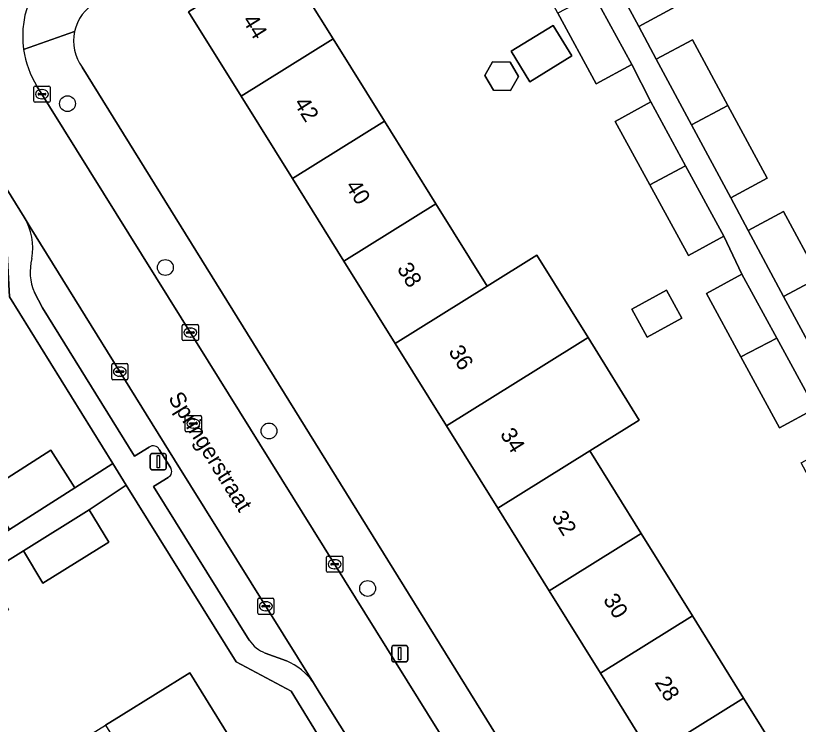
# Model space of a CAD drawing. Extents: x 160030 to 160839, y 385325 to 386450.
# Drawn here: x 160337.33 to 160385.75, y 386132 to 386175.84 of the extents above; entities that cross this region are included whole.
import ezdxf

# ---------------------------------------------------------------- set-up
doc = ezdxf.new("R2010")
doc.units = 0
for name, color, linetype in [('IMGEO_Boom', 7, 'Continuous'), ('IMGEO_Erf', 7, 'Continuous'), ('IMGEO_Kolk', 7, 'Continuous'), ('IMGEO_Lichtmast', 7, 'Continuous'), ('IMGEO_Openbare_ruimte_label', 7, 'Continuous'), ('IMGEO_Pand', 7, 'Continuous'), ('IMGEO_Pand_nummerreeks', 7, 'Continuous'), ('IMGEO_Parkeervlak_open', 7, 'Continuous'), ('IMGEO_Rijbaan_lokaal_open', 7, 'Continuous'), ('IMGEO_Rioolput', 7, 'Continuous'), ('IMGEO_Voetpad_open', 7, 'Continuous')]:
    doc.layers.add(name, color=color, linetype=linetype)

msp = doc.modelspace()

# ---------------------------------------------------------------- linework, layer by layer
at = {"layer": 'IMGEO_Boom'}
for centre in [(160340.54, 386170.396), (160346.596, 386160.261), (160353.007, 386150.151), (160359.103, 386140.41)]:
    msp.add_circle(centre, 0.489, dxfattribs=at)
at = {"layer": 'IMGEO_Erf'}
for points in [[(160386.456, 386204.216), (160366.397, 386191.699), (160368.364, 386188.756), (160370.398, 386190.026), (160372.892, 386185.907), (160370.857, 386184.636), (160371.277, 386183.751), (160373.496, 386184.948), (160375.684, 386180.893), (160378.121, 386176.378), (160375.889, 386175.174), (160376.956, 386173.146), (160379.191, 386174.352), (160381.389, 386170.279), (160383.816, 386165.782), (160381.567, 386164.569), (160382.635, 386162.54), (160384.828, 386163.723), (160387.034, 386159.635)], [(160380.059, 386158.644), (160382.254, 386159.841), (160381.145, 386162.194), (160378.95, 386160.997), (160376.563, 386165.373), (160374.42, 386169.302), (160376.615, 386170.499), (160375.446, 386172.828), (160373.251, 386171.631), (160370.876, 386175.985), (160368.721, 386179.936), (160370.916, 386181.133), (160369.675, 386183.865), (160367.589, 386182.567), (160365.026, 386186.686), (160367.112, 386187.984), (160365.243, 386190.979), (160342.312, 386176.669)], [(160376.673, 386130.076), (160373.499, 386135.173), (160370.324, 386140.271), (160367.15, 386145.368), (160363.976, 386150.466), (160360.802, 386155.563), (160357.628, 386160.661), (160354.453, 386165.759), (160351.279, 386170.856), (160348.03, 386176.074), (160353.721, 386179.618), (160356.97, 386174.4), (160360.144, 386169.303), (160363.319, 386164.205), (160366.493, 386159.107), (160369.564, 386161.019), (160372.737, 386155.922), (160375.911, 386150.824), (160372.841, 386148.912), (160376.015, 386143.815), (160379.19, 386138.717), (160382.364, 386133.62), (160385.538, 386128.522)], [(160341.444, 386172.646), (160376.697, 386115.797)], [(160323.179, 386138.988), (160324.786, 386136.357), (160326.683, 386137.623), (160325.077, 386140.255), (160329.187, 386142.765), (160333.374, 386145.322), (160334.981, 386142.691), (160336.951, 386144.064), (160335.473, 386146.382), (160339.517, 386148.959), (160340.994, 386146.641), (160343.347, 386148.141), (160336.954, 386158.446), (160336.745, 386162.264), (160333.355, 386167.748)], [(160395.89, 386129.127), (160393.518, 386133.476), (160391.36, 386137.432), (160393.555, 386138.629), (160392.361, 386140.915), (160390.405, 386139.848), (160388.05, 386144.211), (160385.912, 386148.174), (160387.831, 386149.22), (160386.784, 386151.536), (160384.589, 386150.339), (160382.194, 386154.73), (160380.059, 386158.644)], [(160356.619, 386130.39), (160354.382, 386134.055), (160350.965, 386135.86), (160344.179, 386146.799), (160341.891, 386145.277), (160343.104, 386143.276), (160339.025, 386140.734), (160337.811, 386142.735), (160335.492, 386141.288), (160336.901, 386139.096), (160332.927, 386136.669), (160328.919, 386134.22), (160327.51, 386136.412), (160325.295, 386134.953), (160326.704, 386132.761), (160322.731, 386130.334)], [(160332.687, 386125.641), (160337.79, 386128.799), (160342.892, 386131.955), (160343.853, 386132.55), (160348.104, 386135.18), (160351.609, 386129.515), (160346.397, 386126.29), (160341.295, 386123.133), (160336.192, 386119.976), (160331.09, 386116.819), (160325.988, 386113.663), (160320.885, 386110.506), (160315.783, 386107.349), (160310.68, 386104.192), (160305.578, 386101.035), (160300.363, 386097.808), (160302.214, 386094.817), (160306.39, 386097.366), (160312.51, 386101.101), (160313.388, 386099.731), (160355.583, 386125.97), (160356.119, 386126.467)]]:
    msp.add_lwpolyline(points, dxfattribs=at)
for points in [[(160369.14, 386171.751), (160367.981, 386173.638), (160370.585, 386175.237), (160371.744, 386173.349)], [(160366.891, 386171.224), (160366.362, 386172.132), (160366.838, 386172.981), (160367.918, 386172.971), (160368.436, 386172.081), (160367.949, 386171.213)], [(160375.451, 386157.68), (160377.601, 386158.852), (160378.54, 386157.13), (160376.39, 386155.958)]]:
    msp.add_lwpolyline(points, close=True, dxfattribs=at)
for centre, radius, start, end in [((160343.671, 386174.271), 2.756, 119.5495, 167.839), ((160343.675, 386174.271), 2.76, 167.8455, 216.0601)]:
    msp.add_arc(centre, radius, start, end, dxfattribs=at)
at = {"layer": 'IMGEO_Kolk'}
for p, q in [((160338.46, 386170.556), (160338.46, 386171.408)), ((160338.535, 386171.482), (160339.387, 386171.482)), ((160338.948, 386171.262), (160338.973, 386171.262)), ((160339.461, 386171.408), (160339.461, 386170.556)), ((160338.719, 386170.976), (160338.719, 386170.988)), ((160339.157, 386170.939), (160338.759, 386170.939)), ((160338.762, 386171.025), (160339.16, 386171.025)), ((160339.203, 386170.988), (160339.203, 386170.976)), ((160339.387, 386170.482), (160338.535, 386170.482)), ((160338.971, 386170.702), (160338.946, 386170.702)), ((160347.714, 386156.736), (160348.566, 386156.736)), ((160347.639, 386155.81), (160347.639, 386156.662)), ((160347.941, 386156.279), (160348.339, 386156.279)), ((160348.127, 386156.516), (160348.152, 386156.516)), ((160348.64, 386156.662), (160348.64, 386155.81)), ((160347.898, 386156.23), (160347.898, 386156.242)), ((160348.336, 386156.193), (160347.938, 386156.193)), ((160348.15, 386155.956), (160348.125, 386155.956)), ((160348.382, 386156.242), (160348.382, 386156.23)), ((160348.566, 386155.736), (160347.714, 386155.736)), ((160343.353, 386154.318), (160344.205, 386154.318)), ((160343.278, 386153.392), (160343.278, 386154.244)), ((160343.58, 386153.861), (160343.978, 386153.861)), ((160343.766, 386154.098), (160343.791, 386154.098)), ((160344.279, 386154.244), (160344.279, 386153.392)), ((160343.537, 386153.812), (160343.537, 386153.824)), ((160343.975, 386153.775), (160343.577, 386153.775)), ((160343.789, 386153.538), (160343.764, 386153.538)), ((160344.021, 386153.824), (160344.021, 386153.812)), ((160344.205, 386153.318), (160343.353, 386153.318)), ((160356.562, 386141.482), (160356.562, 386142.334)), ((160356.637, 386142.408), (160357.489, 386142.408)), ((160357.563, 386142.334), (160357.563, 386141.482)), ((160356.821, 386141.902), (160356.821, 386141.914)), ((160357.259, 386141.865), (160356.861, 386141.865)), ((160356.864, 386141.951), (160357.262, 386141.951)), ((160357.05, 386142.188), (160357.075, 386142.188)), ((160357.305, 386141.914), (160357.305, 386141.902)), ((160357.489, 386141.408), (160356.637, 386141.408)), ((160357.073, 386141.628), (160357.048, 386141.628)), ((160352.385, 386139.807), (160353.237, 386139.807)), ((160352.31, 386138.881), (160352.31, 386139.733)), ((160352.569, 386139.301), (160352.569, 386139.313)), ((160352.612, 386139.35), (160353.01, 386139.35)), ((160352.798, 386139.587), (160352.823, 386139.587)), ((160353.053, 386139.313), (160353.053, 386139.301)), ((160353.311, 386139.733), (160353.311, 386138.881)), ((160353.007, 386139.264), (160352.609, 386139.264)), ((160352.821, 386139.027), (160352.796, 386139.027)), ((160353.237, 386138.807), (160352.385, 386138.807))]:
    msp.add_line(p, q, dxfattribs=at)
for points in [[(160338.46, 386170.556), (160338.46, 386171.408)], [(160338.535, 386171.482), (160339.387, 386171.482)], [(160339.461, 386171.408), (160339.461, 386170.556)], [(160339.387, 386170.482), (160338.535, 386170.482)], [(160347.714, 386156.736), (160348.566, 386156.736)], [(160347.639, 386155.81), (160347.639, 386156.662)], [(160348.64, 386156.662), (160348.64, 386155.81)], [(160348.566, 386155.736), (160347.714, 386155.736)], [(160343.353, 386154.318), (160344.205, 386154.318)], [(160343.278, 386153.392), (160343.278, 386154.244)], [(160344.279, 386154.244), (160344.279, 386153.392)], [(160344.205, 386153.318), (160343.353, 386153.318)], [(160356.562, 386141.482), (160356.562, 386142.334)], [(160356.637, 386142.408), (160357.489, 386142.408)], [(160357.563, 386142.334), (160357.563, 386141.482)], [(160357.489, 386141.408), (160356.637, 386141.408)], [(160352.385, 386139.807), (160353.237, 386139.807)], [(160352.31, 386138.881), (160352.31, 386139.733)], [(160353.311, 386139.733), (160353.311, 386138.881)], [(160353.237, 386138.807), (160352.385, 386138.807)]]:
    msp.add_lwpolyline(points, dxfattribs=at)
for centre, radius, start, end in [((160338.537, 386171.406), 0.0765, 91.552, 178.448), ((160338.537, 386171.406), 0.0765, 91.552, 178.448), ((160339.385, 386171.406), 0.0765, 1.552, 88.448), ((160339.385, 386171.406), 0.0765, 1.552, 88.448), ((160338.759, 386170.985), 0.0403, 85.8775, 175.7526), ((160338.756, 386170.975), 0.0366, 178.938, 274.7102), ((160339.16, 386170.982), 0.043, 264.8664, 352.4533), ((160339.164, 386170.987), 0.0386, 1.7309, 96.639), ((160338.537, 386170.558), 0.0765, 181.552, 268.448), ((160338.537, 386170.558), 0.0765, 181.552, 268.448), ((160339.385, 386170.558), 0.0765, 271.552, 358.448), ((160339.385, 386170.558), 0.0765, 271.552, 358.448), ((160347.716, 386156.66), 0.0765, 91.552, 178.448), ((160347.716, 386156.66), 0.0765, 91.552, 178.448), ((160348.564, 386156.66), 0.0765, 1.552, 88.448), ((160348.564, 386156.66), 0.0765, 1.552, 88.448), ((160347.938, 386156.239), 0.0403, 85.8775, 175.7526), ((160348.343, 386156.241), 0.0386, 1.7309, 96.639), ((160347.716, 386155.812), 0.0765, 181.552, 268.448), ((160347.716, 386155.812), 0.0765, 181.552, 268.448), ((160347.935, 386156.229), 0.0366, 178.938, 274.7102), ((160348.339, 386156.236), 0.043, 264.8664, 352.4533), ((160348.564, 386155.812), 0.0765, 271.552, 358.448), ((160348.564, 386155.812), 0.0765, 271.552, 358.448), ((160343.355, 386154.242), 0.0765, 91.552, 178.448), ((160343.355, 386154.242), 0.0765, 91.552, 178.448), ((160344.203, 386154.242), 0.0765, 1.552, 88.448), ((160344.203, 386154.242), 0.0765, 1.552, 88.448), ((160343.577, 386153.821), 0.0403, 85.8775, 175.7526), ((160343.982, 386153.823), 0.0386, 1.7309, 96.639), ((160343.355, 386153.394), 0.0765, 181.552, 268.448), ((160343.355, 386153.394), 0.0765, 181.552, 268.448), ((160343.574, 386153.811), 0.0366, 178.938, 274.7102), ((160343.978, 386153.818), 0.043, 264.8664, 352.4533), ((160344.203, 386153.394), 0.0765, 271.552, 358.448), ((160344.203, 386153.394), 0.0765, 271.552, 358.448), ((160356.639, 386142.332), 0.0765, 91.552, 178.448), ((160356.639, 386142.332), 0.0765, 91.552, 178.448), ((160357.487, 386142.332), 0.0765, 1.552, 88.448), ((160357.487, 386142.332), 0.0765, 1.552, 88.448), ((160356.861, 386141.911), 0.0403, 85.8775, 175.7526), ((160356.858, 386141.901), 0.0366, 178.938, 274.7102), ((160357.262, 386141.908), 0.043, 264.8664, 352.4533), ((160357.266, 386141.913), 0.0386, 1.7309, 96.639), ((160356.639, 386141.484), 0.0765, 181.552, 268.448), ((160356.639, 386141.484), 0.0765, 181.552, 268.448), ((160357.487, 386141.484), 0.0765, 271.552, 358.448), ((160357.487, 386141.484), 0.0765, 271.552, 358.448), ((160352.387, 386139.731), 0.0765, 91.552, 178.448), ((160352.387, 386139.731), 0.0765, 91.552, 178.448), ((160353.235, 386139.731), 0.0765, 1.552, 88.448), ((160353.235, 386139.731), 0.0765, 1.552, 88.448), ((160352.609, 386139.31), 0.0403, 85.8775, 175.7526), ((160353.014, 386139.312), 0.0386, 1.7309, 96.639), ((160352.387, 386138.883), 0.0765, 181.552, 268.448), ((160352.387, 386138.883), 0.0765, 181.552, 268.448), ((160352.606, 386139.3), 0.0366, 178.938, 274.7102), ((160353.01, 386139.307), 0.043, 264.8664, 352.4533), ((160353.235, 386138.883), 0.0765, 271.552, 358.448), ((160353.235, 386138.883), 0.0765, 271.552, 358.448)]:
    msp.add_arc(centre, radius, start, end, dxfattribs=at)
for centre, major_axis, ratio, start_param, end_param in [((160338.947, 386170.982), (-0.387, 0.002), 0.722429, 4.712389, 7.853982), ((160338.972, 386170.982), (-0.39, 0.002), 0.717154, 1.570796, 4.712389), ((160348.126, 386156.236), (-0.387, 0.002), 0.722429, 4.712389, 7.853982), ((160348.151, 386156.236), (-0.39, 0.002), 0.717154, 1.570796, 4.712389), ((160343.765, 386153.818), (-0.387, 0.002), 0.722429, 4.712389, 7.853982), ((160343.79, 386153.818), (-0.39, 0.002), 0.717154, 1.570796, 4.712389), ((160357.049, 386141.908), (-0.387, 0.002), 0.722429, 4.712389, 7.853982), ((160357.074, 386141.908), (-0.39, 0.002), 0.717154, 1.570796, 4.712389), ((160352.797, 386139.307), (-0.387, 0.002), 0.722429, 4.712389, 7.853982), ((160352.822, 386139.307), (-0.39, 0.002), 0.717154, 1.570796, 4.712389)]:
    msp.add_ellipse(centre, major_axis=major_axis, ratio=ratio, start_param=start_param, end_param=end_param, dxfattribs=at)
at = {"layer": 'IMGEO_Lichtmast'}
for p, q in [((160345.659, 386147.852), (160345.659, 386148.652)), ((160345.659, 386148.652), (160345.659, 386147.852)), ((160345.759, 386148.752), (160346.549, 386148.752)), ((160346.549, 386148.752), (160345.759, 386148.752)), ((160346.649, 386148.652), (160346.649, 386147.852)), ((160346.649, 386147.852), (160346.649, 386148.652)), ((160346.549, 386147.752), (160345.759, 386147.752)), ((160345.759, 386147.752), (160346.549, 386147.752)), ((160360.595, 386135.977), (160360.595, 386136.777)), ((160360.595, 386136.777), (160360.595, 386135.977)), ((160360.695, 386136.877), (160361.485, 386136.877)), ((160361.485, 386136.877), (160360.695, 386136.877)), ((160361.585, 386136.777), (160361.585, 386135.977)), ((160361.585, 386135.977), (160361.585, 386136.777)), ((160361.485, 386135.877), (160360.695, 386135.877)), ((160360.695, 386135.877), (160361.485, 386135.877))]:
    msp.add_line(p, q, dxfattribs=at)
for points in [[(160346.079, 386148.627), (160346.229, 386148.627), (160346.229, 386147.877), (160346.079, 386147.877), (160346.079, 386148.627)], [(160361.015, 386136.752), (160361.165, 386136.752), (160361.165, 386136.002), (160361.015, 386136.002), (160361.015, 386136.752)]]:
    msp.add_lwpolyline(points, dxfattribs=at)
for centre, start, end in [((160345.759, 386148.652), 90, 180), ((160345.759, 386148.652), 90, 180), ((160346.549, 386148.652), 0, 90), ((160346.549, 386148.652), 360, 90), ((160345.759, 386147.852), 180, 270), ((160345.759, 386147.852), 180, 270), ((160346.549, 386147.852), 270, 0), ((160346.549, 386147.852), 270, 0), ((160360.695, 386136.777), 90, 180), ((160360.695, 386136.777), 90, 180), ((160361.485, 386136.777), 0, 90), ((160361.485, 386136.777), 360, 90), ((160360.695, 386135.977), 180, 270), ((160360.695, 386135.977), 180, 270), ((160361.485, 386135.977), 270, 0), ((160361.485, 386135.977), 270, 0)]:
    msp.add_arc(centre, 0.1, start, end, dxfattribs=at)
at = {"layer": 'IMGEO_Pand'}
for points in [[(160375.684, 386180.893), (160373.453, 386179.688), (160375.889, 386175.174), (160378.121, 386176.378)], [(160356.97, 386174.4), (160353.721, 386179.618), (160348.03, 386176.074), (160351.279, 386170.856)], [(160370.876, 386175.985), (160373.251, 386171.631), (160375.446, 386172.828), (160373.075, 386177.175)], [(160367.981, 386173.638), (160369.14, 386171.751), (160371.744, 386173.349), (160370.585, 386175.237)], [(160351.279, 386170.856), (160354.453, 386165.759), (160360.144, 386169.303), (160356.97, 386174.4)], [(160376.956, 386173.146), (160379.134, 386169.079), (160381.389, 386170.279), (160379.191, 386174.352)], [(160366.362, 386172.132), (160366.891, 386171.224), (160367.949, 386171.213), (160368.436, 386172.081), (160367.918, 386172.971), (160366.838, 386172.981)], [(160378.771, 386166.546), (160376.615, 386170.499), (160374.42, 386169.302), (160376.563, 386165.373)], [(160381.389, 386170.279), (160379.134, 386169.079), (160381.567, 386164.569), (160383.816, 386165.782)], [(160363.319, 386164.205), (160360.144, 386169.303), (160354.453, 386165.759), (160357.628, 386160.661)], [(160376.563, 386165.373), (160378.95, 386160.997), (160381.145, 386162.194), (160378.771, 386166.546)], [(160366.493, 386159.107), (160363.319, 386164.205), (160357.628, 386160.661), (160360.802, 386155.563)], [(160382.635, 386162.54), (160384.828, 386158.477), (160387.034, 386159.635), (160384.828, 386163.723)], [(160372.737, 386155.922), (160369.564, 386161.019), (160366.493, 386159.107), (160360.802, 386155.563), (160363.976, 386150.466), (160369.667, 386154.01)], [(160384.408, 386155.892), (160382.254, 386159.841), (160380.059, 386158.644), (160382.194, 386154.73)], [(160387.034, 386159.635), (160384.828, 386158.477), (160387.26, 386153.97), (160389.453, 386155.153)], [(160375.451, 386157.68), (160376.39, 386155.958), (160378.54, 386157.13), (160377.601, 386158.852)], [(160375.911, 386150.824), (160372.737, 386155.922), (160369.667, 386154.01), (160363.976, 386150.466), (160367.15, 386145.368), (160372.841, 386148.912)], [(160382.194, 386154.73), (160384.589, 386150.339), (160386.784, 386151.536), (160384.408, 386155.892)], [(160340.994, 386146.641), (160339.517, 386148.959), (160335.473, 386146.382), (160336.951, 386144.064)], [(160372.841, 386148.912), (160367.15, 386145.368), (160370.324, 386140.271), (160376.015, 386143.815)], [(160341.891, 386145.277), (160337.811, 386142.735), (160339.025, 386140.734), (160343.104, 386143.276)], [(160379.19, 386138.717), (160376.015, 386143.815), (160370.324, 386140.271), (160373.499, 386135.173)], [(160373.499, 386135.173), (160376.673, 386130.076), (160382.364, 386133.62), (160379.19, 386138.717)], [(160346.397, 386126.29), (160351.609, 386129.515), (160348.104, 386135.18), (160343.853, 386132.55), (160342.892, 386131.955)], [(160385.538, 386128.522), (160382.364, 386133.62), (160376.673, 386130.076), (160379.847, 386124.978)]]:
    msp.add_lwpolyline(points, close=True, dxfattribs=at)
at = {"layer": 'IMGEO_Parkeervlak_open'}
for points in [[(160347.159, 386148.37), (160338.231, 386162.765), (160337.856, 386163.369)], [(160338.504, 386158.72), (160339.001, 386157.761), (160344.695, 386148.581), (160345.6, 386149.144)], [(160346.22, 386149), (160346.906, 386147.896)], [(160355.747, 386134.579), (160347.159, 386148.37)], [(160346.762, 386147.276), (160345.856, 386146.712), (160351.779, 386137.216), (160351.782, 386137.212)], [(160352.769, 386136.411), (160354.079, 386135.926)]]:
    msp.add_lwpolyline(points, dxfattribs=at)
for centre, radius, start, end in [((160334.707, 386161.445), 3.69, 350.1807, 31.4189), ((160341.279, 386159.987), 3.051, 164.2393, 204.5456), ((160345.851, 386148.819), 0.411, 26.1938, 127.655), ((160346.581, 386147.645), 0.411, 296.1938, 37.655), ((160353.613, 386138.459), 2.215, 214.2675, 247.6103), ((160352.653, 386132.454), 3.754, 34.4839, 67.6706)]:
    msp.add_arc(centre, radius, start, end, dxfattribs=at)
at = {"layer": 'IMGEO_Rijbaan_lokaal_open'}
for points in [[(160349.241, 386154.465), (160338.651, 386171.478)], [(160334.463, 386168.84), (160337.856, 386163.369), (160338.231, 386162.765), (160347.159, 386148.37), (160355.747, 386134.579), (160356.107, 386134.002), (160361.114, 386125.995), (160363.293, 386122.502)], [(160368.048, 386124.266), (160349.241, 386154.465)]]:
    msp.add_lwpolyline(points, dxfattribs=at)
for centre, radius, start, end in [((160343.623, 386174.571), 5.855, 121.88, 188.137), ((160343.63, 386174.575), 5.863, 188.1638, 211.8796)]:
    msp.add_arc(centre, radius, start, end, dxfattribs=at)
at = {"layer": 'IMGEO_Rioolput'}
for p, q in [((160347.827, 386150.178), (160347.827, 386151.03)), ((160347.902, 386151.104), (160348.754, 386151.104)), ((160348.828, 386151.03), (160348.828, 386150.178)), ((160348.086, 386150.598), (160348.086, 386150.61)), ((160348.524, 386150.561), (160348.126, 386150.561)), ((160348.129, 386150.647), (160348.527, 386150.647)), ((160348.315, 386150.884), (160348.34, 386150.884)), ((160348.57, 386150.61), (160348.57, 386150.598)), ((160348.754, 386150.104), (160347.902, 386150.104)), ((160348.338, 386150.324), (160348.313, 386150.324))]:
    msp.add_line(p, q, dxfattribs=at)
for points in [[(160347.827, 386150.178), (160347.827, 386151.03)], [(160347.902, 386151.104), (160348.754, 386151.104)], [(160348.828, 386151.03), (160348.828, 386150.178)], [(160348.754, 386150.104), (160347.902, 386150.104)]]:
    msp.add_lwpolyline(points, dxfattribs=at)
for centre, radius, start, end in [((160347.904, 386151.028), 0.0765, 91.552, 178.448), ((160347.904, 386151.028), 0.0765, 91.552, 178.448), ((160348.752, 386151.028), 0.0765, 1.552, 88.448), ((160348.752, 386151.028), 0.0765, 1.552, 88.448), ((160348.126, 386150.607), 0.0403, 85.8775, 175.7526), ((160348.123, 386150.597), 0.0366, 178.938, 274.7102), ((160348.527, 386150.604), 0.043, 264.8664, 352.4533), ((160348.531, 386150.609), 0.0386, 1.7309, 96.639), ((160347.904, 386150.18), 0.0765, 181.552, 268.448), ((160347.904, 386150.18), 0.0765, 181.552, 268.448), ((160348.752, 386150.18), 0.0765, 271.552, 358.448), ((160348.752, 386150.18), 0.0765, 271.552, 358.448)]:
    msp.add_arc(centre, radius, start, end, dxfattribs=at)
for centre, major_axis, ratio, start_param, end_param in [((160348.314, 386150.604), (-0.387, 0.002), 0.722429, 4.712389, 7.853982), ((160348.339, 386150.604), (-0.39, 0.002), 0.717154, 1.570796, 4.712389)]:
    msp.add_ellipse(centre, major_axis=major_axis, ratio=ratio, start_param=start_param, end_param=end_param, dxfattribs=at)
at = {"layer": 'IMGEO_Voetpad_open'}
for points in [[(160387.26, 386153.97), (160384.828, 386158.477), (160382.635, 386162.54), (160381.567, 386164.569), (160379.134, 386169.079), (160376.956, 386173.146), (160375.889, 386175.174), (160373.453, 386179.688), (160371.277, 386183.751), (160370.857, 386184.636), (160368.364, 386188.756), (160366.397, 386191.699), (160365.243, 386190.979), (160367.112, 386187.984), (160369.675, 386183.865), (160370.916, 386181.133), (160373.075, 386177.175), (160375.446, 386172.828), (160376.615, 386170.499), (160378.771, 386166.546), (160381.145, 386162.194), (160382.254, 386159.841), (160384.408, 386155.892), (160386.784, 386151.536)], [(160337.826, 386173.742), (160340.977, 386174.852)], [(160340.977, 386174.852), (160337.826, 386173.742)], [(160325.931, 386085.044), (160328.868, 386084.732), (160377.382, 386114.693), (160376.697, 386115.797), (160341.444, 386172.646)], [(160338.651, 386171.478), (160349.241, 386154.465), (160368.048, 386124.266)], [(160337.856, 386163.369), (160334.463, 386168.84)], [(160333.355, 386167.748), (160336.745, 386162.264), (160336.954, 386158.446), (160343.347, 386148.141), (160344.179, 386146.799), (160350.965, 386135.86), (160354.382, 386134.055), (160356.619, 386130.39), (160356.957, 386129.732)], [(160345.6, 386149.144), (160344.695, 386148.581), (160339.001, 386157.761), (160338.504, 386158.72)], [(160346.906, 386147.896), (160346.22, 386149)], [(160351.782, 386137.212), (160351.779, 386137.216), (160345.856, 386146.712), (160346.762, 386147.276)], [(160354.079, 386135.926), (160352.769, 386136.411)], [(160313.409, 386096.468), (160319.518, 386100.287), (160319.552, 386100.231), (160324.78, 386091.706), (160326.17, 386092.56), (160320.972, 386101.06), (160337.622, 386111.408), (160341.88, 386104.496), (160343.284, 386105.352), (160339.026, 386112.29), (160346.775, 386117.126), (160361.114, 386125.995), (160356.107, 386134.002), (160355.747, 386134.579)]]:
    msp.add_lwpolyline(points, dxfattribs=at)
msp.add_lwpolyline([(160331.557, 386138.884), (160335.492, 386141.288), (160337.811, 386142.735), (160341.891, 386145.277), (160344.179, 386146.799), (160343.347, 386148.141), (160340.994, 386146.641), (160336.951, 386144.064), (160334.981, 386142.691), (160330.813, 386140.145), (160326.683, 386137.623), (160324.786, 386136.357), (160320.618, 386133.811), (160316.488, 386131.289), (160314.514, 386130.009), (160314.828, 386129.52), (160315.337, 386128.728), (160317.357, 386130.104), (160321.36, 386132.549), (160325.295, 386134.953), (160327.51, 386136.412)], close=True, dxfattribs=at)
for centre, radius, start, end in [((160343.623, 386174.571), 5.855, 121.88, 188.137), ((160343.671, 386174.271), 2.756, 119.5495, 167.839), ((160343.675, 386174.271), 2.76, 167.8455, 216.0601), ((160343.63, 386174.575), 5.863, 188.1638, 211.8796), ((160334.707, 386161.445), 3.69, 350.1807, 31.4189), ((160341.279, 386159.987), 3.051, 164.2393, 204.5456), ((160345.851, 386148.819), 0.411, 26.1938, 127.655), ((160346.581, 386147.645), 0.411, 296.1938, 37.655), ((160353.613, 386138.459), 2.215, 214.2675, 247.6103), ((160352.653, 386132.454), 3.754, 34.4839, 67.6706)]:
    msp.add_arc(centre, radius, start, end, dxfattribs=at)

# ---------------------------------------------------------------- texts
at = {"layer": 'IMGEO_Openbare_ruimte_label'}
msp.add_text('Springerstraat', height=1, rotation=301.9568, dxfattribs=at).set_placement((160346.737, 386152.184))
at = {"layer": 'IMGEO_Pand_nummerreeks'}
for s, rotation, p in [('44', 301.9103, (160351.326, 386175.548)), ('42', 301.9103, (160354.512, 386170.432)), ('40', 301.9103, (160357.703, 386165.307)), ('38', 301.9103, (160360.89, 386160.188)), ('36', 301.9078, (160364.076, 386155.071)), ('34', 301.9078, (160367.264, 386149.952)), ('32', 301.9078, (160370.45, 386144.836)), ('30', 301.9103, (160373.641, 386139.712)), ('28', 301.9103, (160376.829, 386134.593))]:
    msp.add_text(s, height=1, rotation=rotation, dxfattribs=at).set_placement(p)

doc.saveas('drawing.dxf')
